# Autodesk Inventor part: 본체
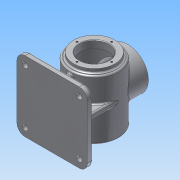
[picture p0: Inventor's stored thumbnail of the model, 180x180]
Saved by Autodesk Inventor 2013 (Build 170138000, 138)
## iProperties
Created: 2015-07
Part Number: 본체
Material: 알루미늄 6061
Document SubType Name: Modeling
Designer: Administrator
Density: 2.71 g/cm^3
Mass: 1241.45 g
Surface Area: 1266.13 cm^2
Volume: 458.098 cm^3
Author: Administrator
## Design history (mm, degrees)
sketch "스케치1"
  geometry: C1 r 45 at (0, 0); 1 further point
  constraints: 1 centre point, 1 coincident
  dimensions: "d0" = 90 diameter of C1
extrude "돌출1" new body sketch "스케치1" distance "d2" = 110; taper "d3" = 0 deg
sketch "스케치2"
  geometry: C1 r 38 at (0, 0); 1 further point
  constraints: 1 centre point, 1 coincident
  dimensions: "d4" = 76 diameter of C1
extrude "돌출2" join sketch "스케치2" distance "d6" = 7; taper "d7" = 0 deg
node "작업 평면1"
sketch "스케치3"
  geometry: L1 (-65, -68)-(65, -68); L2 (65, -68)-(65, -78); L3 (65, -78)-(-65, -78); L4 (-65, -78)-(-65, -68); 2 further points
  constraints: 8 end point, 2 parallel, 1 horizontal, 1 midpoint, 1 perpendicular, 1 vertical alignment
  dimensions: "d9" = 10 distance of L1.end L2.end; "d11" = 78 distance from line of L3 point (0, 0); "d12" = 130 distance of L1.start L1.end
extrude "돌출3" join sketch "스케치3" stored distance "d13" = 110; taper "d14" = 0 deg
node "작업 평면2"
sketch "스케치4"
  geometry: L1 (-29.951, 105)-(-73.534, 105); L2 (-73.534, 105)-(-73.534, 15); L3 (-73.534, 15)-(-29.951, 15); L4 (-29.951, 15)-(-29.951, 105); L5 (-78, 115)-(-68, 115) reference; L6 (-78, 115)-(-78, 5) reference; 1 further point
  constraints: 8 end point, 2 parallel, 1 horizontal, 1 perpendicular
  dimensions: "d16" = 43.58242 distance of L2.end L3.end; "d18" = 90 distance of L1.end L2.end; "d19" = 10 distance between parallel lines of L5 L1; "d20" = 4.46621 distance between parallel lines of L6 L2
extrude "돌출4" join sketch "스케치4" stored distance "d21" = 10; taper "d22" = 0 deg
sketch "스케치5"
  geometry: L1 (-45, 0)-(45, 0); L2 (45, 0)-(45, -73); L3 (45, -73)-(-45, -73); L4 (-45, -73)-(-45, 0); L5 (-65, -78)-(65, -78) reference; 2 further points
  constraints: 8 end point, 2 parallel, 1 coincident, 1 horizontal, 1 midpoint, 1 perpendicular
  dimensions: "d23" = 90 distance of L1.start L1.end; "d25" = 5 distance between parallel lines of L5 L3; "d26" = 73 distance of L1.end L2.end
extrude "돌출5" join sketch "스케치5" stored distance "d27" = 10; taper "d28" = 0 deg
node "작업 평면3"
sketch "스케치6"
  geometry: L1 (0, 0)-(130, 0) reference; C1 r 38 at (65, -55); 1 further point
  constraints: 1 centre point, 1 vertical alignment
  dimensions: "d30" = 76 diameter of C1; "d32" = 55 distance from line of C1.centre L1
extrude "돌출6" join sketch "스케치6" stored distance "d33" = 10; taper "d34" = 0 deg
sketch "스케치7"
  geometry: L1 (0, 110)-(130, 110) reference; L2 (0, 110)-(0, 0) reference; C1 r 7.5 at (15, 105); C2 r 7.5 at (115, 105); C3 r 7.5 at (115, 5); C4 r 7.5 at (15, 5); 1 further point
  constraints: 4 centre point, 3 equal radius, 2 horizontal alignment, 2 vertical alignment
  dimensions: "d35" = 15 diameter of C1; "d37" = 100 distance of C1.centre C2.centre; "d38" = 100 distance of C3.centre C2.centre; "d40" = 15 distance from line of L2 C1.centre; "d112" = 5 distance from line of C2.centre L1
extrude "돌출7" join sketch "스케치7" distance "d41" = 3; taper "d42" = 0 deg
sketch "스케치8"
  geometry: C1 r 5 at (0, 100); C2 r 5 at (0, 0); C3 r 5 at (100, 0); C4 r 5 at (100, 100); C5 r 7.5 at (0, 100) reference; C6 r 7.5 at (100, 100) reference; C7 r 7.5 at (100, 0) reference; C8 r 7.5 at (0, 0) reference; 1 further point
  constraints: 4 centre point, 4 concentric, 3 equal radius
  dimensions: "d43" = 10 diameter of C1
extrude "돌출8" cut sketch "스케치8" stored distance "d45" = 3; taper "d46" = 0 deg
sketch "스케치9"
  geometry: 5 further points
  constraints: 2 horizontal alignment, 2 vertical alignment
  dimensions: "d47" = 64 distance of point (0, -32) point (0, 32); "d49" = 64 distance of point (-32, 0) point (32, 0); "d50" = 32 distance of point (0, 0) point (0, 32); "d51" = 32 distance of point (-32, 0) point (0, 0)
hole "구멍1" sketch "스케치9" at (0, 32), (0, -32), (-32, 0), (32, 0) diameter "d52" = 3.242; stored, may be unused: countersink angle "d56" = 90 deg, drill point angle "d58" = 118 deg; dims "d53" = 8, "d54" = 4, "d55" = 2, "d57" = 10
sketch "스케치10"
  geometry: L1 (65, -55)-(65, 55) reference; L2 (65, -55)-(-65, -55) reference; 6 further points
  constraints: 2 horizontal alignment, 2 vertical alignment
  dimensions: "d59" = 64 distance of point (0, 32) point (0, -32); "d61" = 64 distance of point (-32, 0) point (32, 0); "d62" = 65 distance from line of L1 point (0, 0); "d63" = 55 distance from line of L2 point (0, 0); "d64" = 32 distance of point (0, 0) point (0, 32); "d65" = 32 distance of point (-32, 0) point (0, 0)
hole "구멍2" sketch "스케치10" at (0, 32), (0, -32), (-32, 0), (32, 0) diameter "d66" = 3.242; stored, may be unused: countersink angle "d70" = 90 deg, drill point angle "d72" = 118 deg; dims "d67" = 8, "d68" = 4, "d69" = 2, "d71" = 10
hole "구멍3" diameter "d75" = 54; stored, may be unused: countersink angle "d79" = 90 deg, drill point angle "d81" = 0 deg; dims "d73" = 10, "d74" = 10, "d76" = 8, "d77" = 4, "d78" = 2, "d80" = 14
hole "구멍4" diameter "d84" = 80; stored, may be unused: countersink angle "d88" = 90 deg, drill point angle "d90" = 0 deg; dims "d82" = 10, "d83" = 10, "d85" = 8, "d86" = 4, "d87" = 2, "d89" = 96
hole "구멍5" diameter "d93" = 54; stored, may be unused: countersink angle "d97" = 90 deg, drill point angle "d99" = 0 deg; dims "d91" = 10, "d92" = 10, "d94" = 8, "d95" = 4, "d96" = 2, "d98" = 40
sketch "스케치11"
  geometry: 2 further points
  constraints: 2 coincident, 1 other
feature "엠보싱1" sketch "스케치11" dims "d16" = 43.58242, "d18" = 90, "d19" = 10, "d20" = 4.46621, "d100" = 0.5, "d101" = 0
sketch "스케치12"
  geometry: L1 (-65, -68)-(65, -68); L2 (65, -68)-(65, -78); L3 (65, -78)-(-65, -78); L4 (-65, -78)-(-65, -68); 3 further points
  constraints: 8 end point, 2 coincident, 2 parallel, 1 horizontal, 1 perpendicular
extrude "돌출9" join sketch "스케치12" distance "d108" = 10; taper "d109" = 0 deg
sketch "스케치13"
  geometry: L1 (-65, -68)-(65, -68); L2 (65, -68)-(65, -78); L3 (65, -78)-(-65, -78); L4 (-65, -78)-(-65, -68); 3 further points
  constraints: 8 end point, 2 coincident, 2 parallel, 1 horizontal, 1 perpendicular
extrude "돌출10" join sketch "스케치13" distance "d110" = 10; taper "d111" = 0 deg
chamfer "모따기2" distance "d113" = 1; stored, may be unused: second distance "d114" = 2, angle "d115" = 45 deg
fillet "모깎기3" dims "d116" = 15, "d117" = 3
fillet "모깎기4" dims "d118" = 3
node "솔리드1"
other parameters: "d15" = 0
